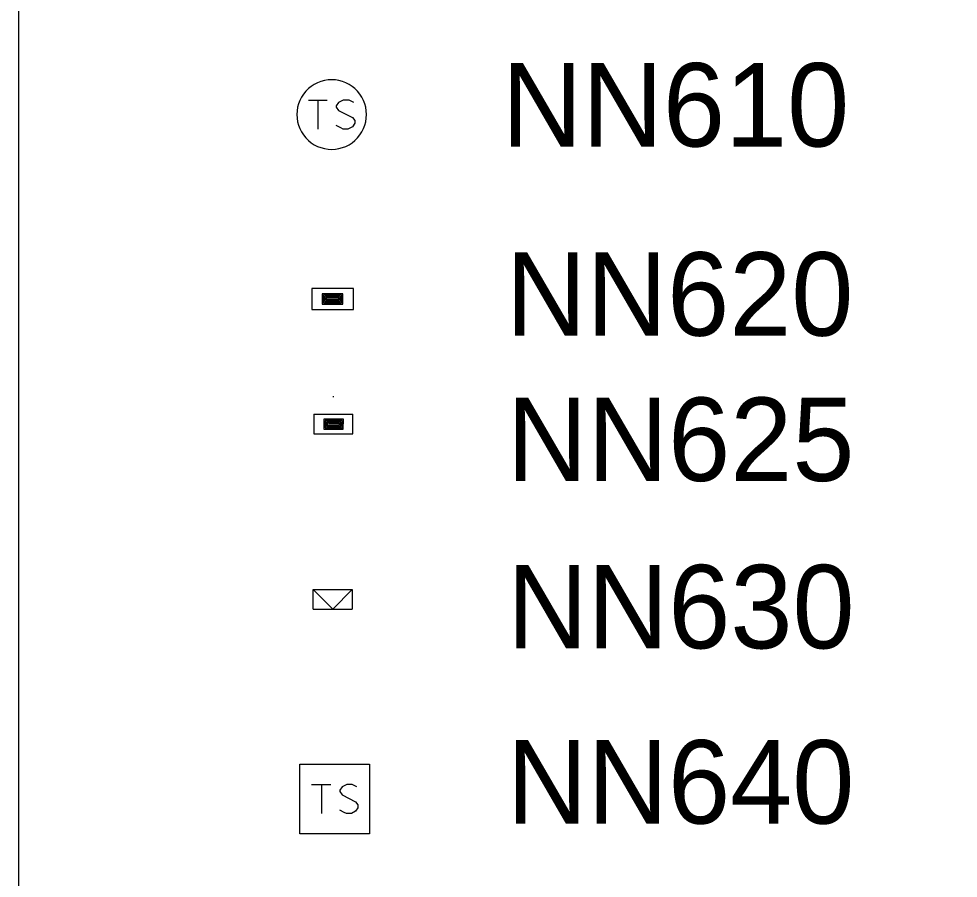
# Model space of a CAD drawing. Extents: x -592825 to -592404, y -1153473 to -1153230.
# Drawn here: x -592679.08 to -592662.21, y -1153412.84 to -1153397.39 of the extents above; entities that cross this region are included whole.
import ezdxf

# ---------------------------------------------------------------- set-up
doc = ezdxf.new("R2010")
doc.units = 0
doc.layers.add('Vrstva 43', color=7, linetype='Continuous')
doc.layers.add('Vrstva 63', color=7, linetype='Continuous')

msp = doc.modelspace()

# ---------------------------------------------------------------- linework, layer by layer
at = {"layer": 'Vrstva 43'}
for points in [[(-592672.837, -1153399.108), (-592672.841, -1153399.042), (-592672.851, -1153398.978), (-592672.868, -1153398.914), (-592672.891, -1153398.853), (-592672.921, -1153398.795), (-592672.957, -1153398.74), (-592672.998, -1153398.689), (-592673.045, -1153398.642), (-592673.095, -1153398.602), (-592673.15, -1153398.566), (-592673.209, -1153398.536), (-592673.269, -1153398.512), (-592673.333, -1153398.496), (-592673.397, -1153398.486), (-592673.463, -1153398.482), (-592673.529, -1153398.486), (-592673.593, -1153398.496), (-592673.657, -1153398.512), (-592673.718, -1153398.536), (-592673.776, -1153398.566), (-592673.831, -1153398.602), (-592673.882, -1153398.642), (-592673.929, -1153398.689), (-592673.969, -1153398.74), (-592674.005, -1153398.795), (-592674.035, -1153398.853), (-592674.059, -1153398.914), (-592674.075, -1153398.978), (-592674.085, -1153399.042), (-592674.089, -1153399.108), (-592674.085, -1153399.174), (-592674.075, -1153399.238), (-592674.059, -1153399.301), (-592674.035, -1153399.362), (-592674.005, -1153399.421), (-592673.969, -1153399.476), (-592673.928, -1153399.526), (-592673.882, -1153399.573), (-592673.831, -1153399.614), (-592673.776, -1153399.65), (-592673.717, -1153399.68), (-592673.657, -1153399.703), (-592673.593, -1153399.72), (-592673.529, -1153399.73), (-592673.463, -1153399.734), (-592673.397, -1153399.73), (-592673.333, -1153399.72), (-592673.269, -1153399.703), (-592673.209, -1153399.68), (-592673.15, -1153399.65), (-592673.095, -1153399.614), (-592673.045, -1153399.573), (-592672.998, -1153399.526), (-592672.957, -1153399.476), (-592672.921, -1153399.421), (-592672.891, -1153399.362), (-592672.868, -1153399.301), (-592672.851, -1153399.238), (-592672.841, -1153399.174), (-592672.837, -1153399.108)], [(-592673.881, -1153398.848), (-592673.547, -1153398.848)], [(-592673.714, -1153398.848), (-592673.714, -1153399.37)], [(-592673.067, -1153398.89), (-592673.151, -1153398.848), (-592673.255, -1153398.848), (-592673.339, -1153398.89), (-592673.38, -1153398.952), (-592673.38, -1153398.974), (-592673.339, -1153399.036), (-592673.088, -1153399.161), (-592673.047, -1153399.214), (-592673.047, -1153399.266), (-592673.088, -1153399.328), (-592673.171, -1153399.37), (-592673.255, -1153399.37), (-592673.297, -1153399.349), (-592673.38, -1153399.308)], [(-592673.071, -1153402.238), (-592673.821, -1153402.238)], [(-592673.821, -1153402.238), (-592673.821, -1153402.612)], [(-592673.263, -1153402.329), (-592673.635, -1153402.329)], [(-592673.635, -1153402.329), (-592673.635, -1153402.518)], [(-592673.287, -1153402.352), (-592673.611, -1153402.352)], [(-592673.611, -1153402.352), (-592673.611, -1153402.494)], [(-592673.287, -1153402.494), (-592673.287, -1153402.352)], [(-592673.263, -1153402.518), (-592673.263, -1153402.329)], [(-592673.071, -1153402.612), (-592673.071, -1153402.238)], [(-592673.635, -1153402.518), (-592673.263, -1153402.518)], [(-592673.611, -1153402.494), (-592673.287, -1153402.494)], [(-592673.587, -1153402.376), (-592673.588, -1153402.471)], [(-592673.588, -1153402.471), (-592673.31, -1153402.471)], [(-592673.31, -1153402.376), (-592673.587, -1153402.376)], [(-592673.335, -1153402.4), (-592673.565, -1153402.4)], [(-592673.565, -1153402.4), (-592673.564, -1153402.446)], [(-592673.564, -1153402.446), (-592673.334, -1153402.447)], [(-592673.543, -1153402.423), (-592673.355, -1153402.424)], [(-592673.334, -1153402.447), (-592673.335, -1153402.4)], [(-592673.31, -1153402.471), (-592673.31, -1153402.376)], [(-592673.821, -1153402.612), (-592673.071, -1153402.612)], [(-592673.426, -1153404.184), (-592673.441, -1153404.184)], [(-592673.785, -1153404.496), (-592673.785, -1153404.846)], [(-592673.785, -1153404.496), (-592673.081, -1153404.496)], [(-592673.081, -1153404.846), (-592673.081, -1153404.496)], [(-592673.253, -1153404.585), (-592673.603, -1153404.585)], [(-592673.603, -1153404.585), (-592673.603, -1153404.762)], [(-592673.275, -1153404.61), (-592673.583, -1153404.61)], [(-592673.583, -1153404.61), (-592673.583, -1153404.74)], [(-592673.297, -1153404.63), (-592673.559, -1153404.63)], [(-592673.559, -1153404.63), (-592673.559, -1153404.718)], [(-592673.559, -1153404.718), (-592673.298, -1153404.718)], [(-592673.32, -1153404.652), (-592673.539, -1153404.652)], [(-592673.539, -1153404.652), (-592673.539, -1153404.698)], [(-592673.539, -1153404.698), (-592673.321, -1153404.698)], [(-592673.339, -1153404.674), (-592673.517, -1153404.674)], [(-592673.321, -1153404.698), (-592673.32, -1153404.652)], [(-592673.298, -1153404.718), (-592673.297, -1153404.63)], [(-592673.276, -1153404.74), (-592673.275, -1153404.61)], [(-592673.254, -1153404.762), (-592673.253, -1153404.585)], [(-592673.785, -1153404.846), (-592673.081, -1153404.846)], [(-592673.603, -1153404.762), (-592673.254, -1153404.762)], [(-592673.583, -1153404.74), (-592673.276, -1153404.74)], [(-592673.443, -1153407.998), (-592673.793, -1153407.648)], [(-592673.793, -1153407.998), (-592673.793, -1153407.648), (-592673.093, -1153407.648), (-592673.093, -1153407.998)], [(-592673.443, -1153407.998), (-592673.093, -1153407.648)], [(-592673.793, -1153407.998), (-592673.093, -1153407.998)], [(-592674.035, -1153412.039), (-592674.034, -1153410.787)], [(-592674.034, -1153410.787), (-592672.783, -1153410.787)], [(-592672.783, -1153410.787), (-592672.782, -1153412.039)], [(-592673.825, -1153411.152), (-592673.481, -1153411.152)], [(-592673.648, -1153411.152), (-592673.648, -1153411.674)], [(-592673.011, -1153411.194), (-592673.095, -1153411.152), (-592673.189, -1153411.152), (-592673.273, -1153411.194), (-592673.314, -1153411.256), (-592673.314, -1153411.277), (-592673.273, -1153411.34), (-592673.033, -1153411.465), (-592672.991, -1153411.518), (-592672.991, -1153411.57), (-592673.033, -1153411.632), (-592673.105, -1153411.674), (-592673.199, -1153411.674), (-592673.241, -1153411.653), (-592673.314, -1153411.612)], [(-592672.782, -1153412.039), (-592674.035, -1153412.039)]]:
    msp.add_lwpolyline(points, dxfattribs=at)
at = {"layer": 'Vrstva 63'}
msp.add_lwpolyline([(-592679.084, -1153338.599), (-592600.649, -1153338.599), (-592600.649, -1153436.347), (-592679.084, -1153436.347)], close=True, dxfattribs=at)

# ---------------------------------------------------------------- texts
for s, p in [('NN610', (-592670.409, -1153399.683)), ('NN620', (-592670.334, -1153403.084)), ('NN625', (-592670.316, -1153405.696)), ('NN630', (-592670.313, -1153408.705)), ('NN640', (-592670.317, -1153411.855))]:
    msp.add_text(s, height=1.5, dxfattribs=at).set_placement(p)

doc.saveas('drawing.dxf')
